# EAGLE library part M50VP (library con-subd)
SUB-D
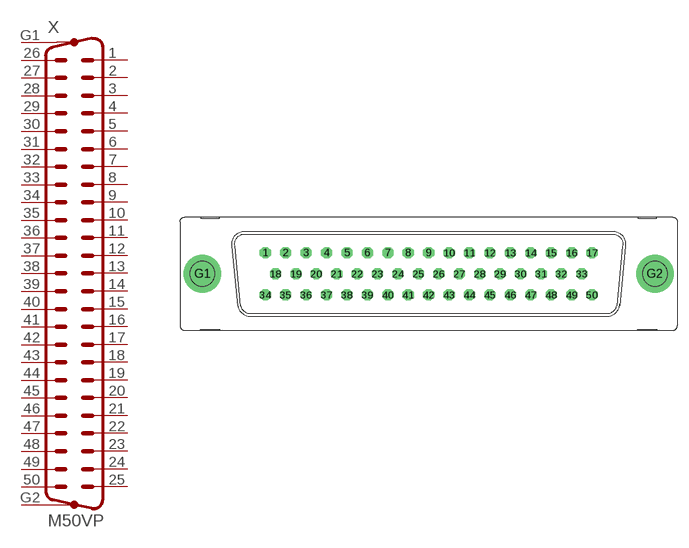
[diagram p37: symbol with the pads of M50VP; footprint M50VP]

Designator prefix X

## M50VP (OC_FARNELL: unknown; OC_NEWARK: unknown)  [M50VP]
1  1  pas
2  2  pas
3  3  pas
4  4  pas
5  5  pas
6  6  pas
7  7  pas
8  8  pas
9  9  pas
10  10  pas
11  11  pas
12  12  pas
13  13  pas
14  14  pas
15  15  pas
16  16  pas
17  17  pas
18  18  pas
19  19  pas
20  20  pas
21  21  pas
22  22  pas
23  23  pas
24  24  pas
25  25  pas
26  26  pas
27  27  pas
28  28  pas
29  29  pas
30  30  pas
31  31  pas
32  32  pas
33  33  pas
34  34  pas
35  35  pas
36  36  pas
37  37  pas
38  38  pas
39  39  pas
40  40  pas
41  41  pas
42  42  pas
43  43  pas
44  44  pas
45  45  pas
46  46  pas
47  47  pas
48  48  pas
49  49  pas
50  50  pas
G1  G1  pas
G2  G2  pas

## Footprint M50VP (pad centres in mm)
SUB-D
drill 1.016 octagon: 1 -22.073,2.845; 2 -19.329,2.845; 3 -16.561,2.845; 4 -13.792,2.845; 5 -11.049,2.845; 6 -8.28,2.845; 7 -5.512,2.845; 8 -2.769,2.845; 9 0,2.845; 10 2.769,2.845; 11 5.512,2.845; 12 8.28,2.845; 13 11.049,2.845; 14 13.792,2.845; 15 16.561,2.845; 16 19.329,2.845; 17 22.073,2.845; 18 -20.701,0; 19 -17.932,0; 20 -15.189,0; 21 -12.421,0; 22 -9.652,0; 23 -6.909,0; 24 -4.14,0; 25 -1.372,0; 26 1.372,0; 27 4.14,0; 28 6.909,0; 29 9.652,0; 30 12.421,0; 31 15.189,0; 32 17.932,0; 33 20.701,0; 34 -22.073,-2.845; 35 -19.329,-2.845; 36 -16.561,-2.845; 37 -13.792,-2.845; 38 -11.049,-2.845; 39 -8.28,-2.845; 40 -5.512,-2.845; 41 -2.769,-2.845; 42 0,-2.845; 43 2.769,-2.845; 44 5.512,-2.845; 45 8.28,-2.845; 46 11.049,-2.845; 47 13.792,-2.845; 48 16.561,-2.845; 49 19.329,-2.845; 50 22.073,-2.845
drill 3.302 pad 5.08 round: G1 -30.556,0; G2 30.556,0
